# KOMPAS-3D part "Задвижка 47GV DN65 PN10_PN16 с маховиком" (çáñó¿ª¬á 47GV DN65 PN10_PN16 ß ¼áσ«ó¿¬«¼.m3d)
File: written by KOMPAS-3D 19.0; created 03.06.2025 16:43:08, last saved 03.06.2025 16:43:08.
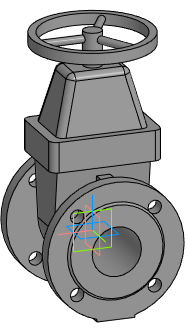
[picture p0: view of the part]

Document properties: Автор: Евгений; Полное имя файла: E:\Dendor Работа Сачек\3D для проекитирвщиков\2.1 Тип 47GV, 47GV.Z Задвижка клиновая фланцевая с обрезиненным клином\stp_Тип 47GV. Задвижка DN40-DN350 с маховиком\Задвижка 47GV DN65 PN10_PN16 с маховиком.m3d

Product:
- Part/product: Задвижка 47GV DN65 PN10_PN16 с маховиком

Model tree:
1. Операция без истории:1  (labels: Задвижка 47GV DN65 PN10_PN16 с маховиком)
